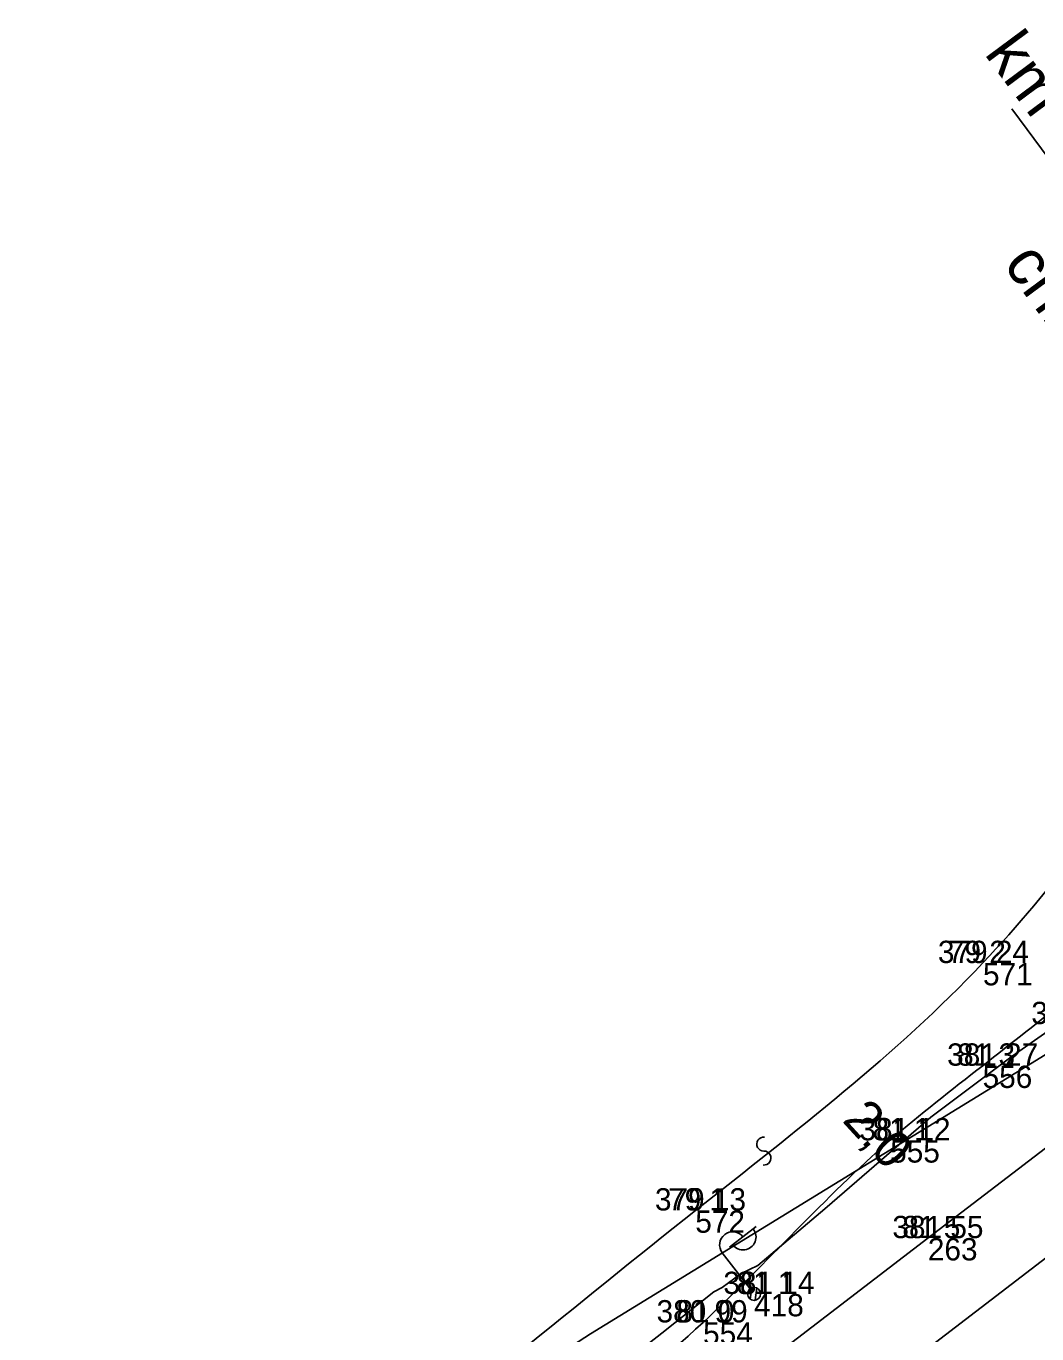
# Model space of a CAD drawing. Extents: x -514509 to -512782, y -1144610 to -1143439.
# Drawn here: x -513789.4 to -513735, y -1143931.3 to -1143860.8 of the extents above; entities that cross this region are included whole.
import ezdxf

# ---------------------------------------------------------------- set-up
doc = ezdxf.new("R2010")
doc.units = 0
for name, color, linetype in [('Vrstva 1', 7, 'Continuous'), ('Vrstva 10', 7, 'Continuous'), ('Vrstva 11', 7, 'Continuous'), ('Vrstva 18', 7, 'Continuous'), ('Vrstva 19', 7, 'Continuous'), ('Vrstva 57', 7, 'Continuous'), ('Vrstva 58', 7, 'Continuous'), ('Vrstva 59', 7, 'Continuous'), ('Vrstva 6', 7, 'Continuous'), ('Vrstva 60', 7, 'Continuous'), ('Vrstva 62', 7, 'Continuous')]:
    doc.layers.add(name, color=color, linetype=linetype)

msp = doc.modelspace()

# ---------------------------------------------------------------- linework, layer by layer
at = {"layer": 'Vrstva 1'}
msp.add_lwpolyline([(-513762.897, -1143937.295), (-513755.156, -1143931.215), (-513752.352, -1143928.991), (-513751.904, -1143928.751), (-513750.881, -1143928.002), (-513749.99, -1143927.567), (-513746.371, -1143924.523), (-513740.66, -1143919.588), (-513736.28, -1143916.302), (-513730.038, -1143911.923)], dxfattribs=at)
at = {"layer": 'Vrstva 10'}
for points in [[(-513758.996, -1143931.25), (-513726.599, -1143911.373), (-513730.516, -1143905.166)], [(-513758.996, -1143931.25), (-513726.599, -1143911.373), (-513730.516, -1143905.166)], [(-514025.149, -1144123.322), (-513986.763, -1144090.342), (-513957.919, -1144069.739), (-513914.955, -1144044.203), (-513897.091, -1144037.29), (-513901.487, -1144029.673), (-513902.648, -1144013.079), (-513904.872, -1144006.744), (-513902.386, -1144000.442), (-513898.213, -1143983.882), (-513883.45, -1143978.334), (-513880.104, -1143957.938), (-513880.595, -1143949.403), (-513873.972, -1143977.51), (-513847.31, -1143967.987), (-513854.293, -1143956.979), (-513854.953, -1143942.972), (-513846.666, -1143942.117), (-513841, -1143972.71), (-513831.435, -1143973.145), (-513796.384, -1143955.482), (-513758.996, -1143931.25)], [(-514025.149, -1144123.322), (-513986.763, -1144090.342), (-513957.919, -1144069.739), (-513914.955, -1144044.203), (-513897.091, -1144037.29), (-513901.487, -1144029.673), (-513902.648, -1144013.079), (-513904.872, -1144006.744), (-513902.386, -1144000.442), (-513898.213, -1143983.882), (-513883.45, -1143978.334), (-513880.104, -1143957.938), (-513880.595, -1143949.403), (-513873.972, -1143977.51), (-513847.31, -1143967.987), (-513854.293, -1143956.979), (-513854.953, -1143942.972), (-513846.666, -1143942.117), (-513841, -1143972.71), (-513831.435, -1143973.145), (-513796.384, -1143955.482), (-513758.996, -1143931.25)]]:
    msp.add_lwpolyline(points, dxfattribs=at)
for points in [[(-513674.274, -1143843.477), (-513674.46, -1143843.597), (-513687.396, -1143852.464), (-513702.821, -1143867.073), (-513717.154, -1143882.054), (-513727.841, -1143898.171), (-513737.859, -1143911.275), (-513753.355, -1143924.614), (-513772.465, -1143940.017), (-513793.162, -1143954.594), (-513811.59, -1143964.008), (-513831.445, -1143975.36)], [(-513808.418, -1143998.941), (-513792.063, -1143986.974), (-513776.16, -1143976.17), (-513764.915, -1143968.271), (-513753.689, -1143959.442), (-513740.521, -1143947.369), (-513724.263, -1143934.903), (-513707.902, -1143922.425), (-513689.125, -1143907.833), (-513675.979, -1143896.958), (-513671.6, -1143893.116), (-513670.058, -1143892.633), (-513668.651, -1143892.952)], [(-513754.963, -1143964.828), (-513734.448, -1143946.693), (-513721.252, -1143935.706), (-513704.018, -1143924.219), (-513687.594, -1143911.382), (-513671.785, -1143899.771)], [(-513766.691, -1143941.396), (-513752.939, -1143930.638), (-513742.864, -1143920.831), (-513737.875, -1143916.811), (-513728.639, -1143909.49)]]:
    msp.add_spline(points, degree=3, dxfattribs=at)
at = {"layer": 'Vrstva 18'}
for centre, radius, start, end in [((-513749.674, -1143921.034), 0.376, 84.36247, 270.6736), ((-513749.661, -1143921.787), 0.377, 263.68642, 91.34964)]:
    msp.add_arc(centre, radius, start, end, dxfattribs=at)
at = {"layer": 'Vrstva 19'}
msp.add_lwpolyline([(-513711.337, -1143898.914), (-513736.312, -1143865.258)], dxfattribs=at)
at = {"layer": 'Vrstva 6'}
for p, q in [((-513751.514, -1143926.588), (-513750.073, -1143925.477)), ((-513750.405, -1143928.827), (-513751.902, -1143926.888)), ((-513750.394, -1143929.39), (-513750.315, -1143928.779)), ((-513750.137, -1143929.449), (-513750.051, -1143928.784))]:
    msp.add_line(p, q, dxfattribs=at)
for points in [[(-513827.123, -1143992.273), (-513814.52, -1143984.92), (-513803.868, -1143978.359), (-513784.062, -1143964.604), (-513774.734, -1143957.987), (-513763.96, -1143949.74), (-513753.71, -1143941.89), (-513743.11, -1143933.78), (-513733.1, -1143926.12), (-513722.71, -1143918.17), (-513711.92, -1143909.9), (-513701.89, -1143902.23), (-513691.32, -1143894.14), (-513681.01, -1143886.25), (-513670.75, -1143878.4), (-513660.29, -1143870.39), (-513649.91, -1143862.61), (-513639.176, -1143854.227), (-513628.844, -1143846.318), (-513618.412, -1143838.333), (-513608.54, -1143830.777), (-513601.542, -1143825.421)], [(-513837.119, -1143999.949), (-513820.645, -1143987.315), (-513815.582, -1143983.432), (-513803.497, -1143974.164), (-513802.439, -1143973.353), (-513792.554, -1143965.771), (-513782.63, -1143958.161), (-513771.743, -1143949.811), (-513761.681, -1143942.094), (-513751.239, -1143934.086), (-513740.83, -1143926.1), (-513730.52, -1143918.22), (-513722.302, -1143911.894), (-513710.63, -1143902.943), (-513703.927, -1143897.802), (-513702.403, -1143896.634), (-513690.746, -1143887.7), (-513684.422, -1143881.665), (-513677.637, -1143875.364), (-513669.934, -1143867.896), (-513657.965, -1143856.444)]]:
    msp.add_lwpolyline(points, dxfattribs=at)
msp.add_circle((-513750.192, -1143929.105), 0.35, dxfattribs=at)
msp.add_circle((-513750.192, -1143929.105), 0.35, dxfattribs=at)
for centre, start, end in [((-513750.788, -1143926.039), 216.94625, 38.3514), ((-513751.348, -1143926.46), 37.64883, 217.64883)]:
    msp.add_arc(centre, 0.7, start, end, dxfattribs=at)
at = {"layer": 'Vrstva 60'}
for p, q in [((-513737.86, -1143911.28), (-513737.86, -1143911.28)), ((-513737.88, -1143916.81), (-513737.88, -1143916.81)), ((-513742.86, -1143920.83), (-513742.86, -1143920.83)), ((-513753.36, -1143924.61), (-513753.36, -1143924.61)), ((-513740.83, -1143926.1), (-513740.83, -1143926.1)), ((-513750.19, -1143929.11), (-513750.19, -1143929.11)), ((-513752.94, -1143930.64), (-513752.94, -1143930.64))]:
    msp.add_line(p, q, dxfattribs=at)

# ---------------------------------------------------------------- texts
at = {"layer": 'Vrstva 11'}
msp.add_text('2,0', height=2, rotation=312.54676, dxfattribs=at).set_placement((-513745.486, -1143919.782))
at = {"layer": 'Vrstva 19'}
msp.add_text('km 42,017', height=2.5, rotation=306.57765, dxfattribs=at).set_placement((-513737.826, -1143862.29))
at = {"layer": 'Vrstva 57'}
for s, p in [('79 2 ', (-513739.75, -1143911.28)), ('81 3 ', (-513739.253, -1143916.81)), ('81 1 ', (-513743.808, -1143920.83)), ('79 1 ', (-513754.824, -1143924.61)), ('81 5 ', (-513742.203, -1143926.1)), ('81 1 ', (-513751.138, -1143929.11)), ('81 0 ', (-513754.378, -1143930.64))]:
    msp.add_text(s, height=1.2, dxfattribs=at).set_placement(p)
at = {"layer": 'Vrstva 58'}
for s, p in [('379 24', (-513740.288, -1143911.28)), ('381 17', (-513735.256, -1143914.57)), ('381 27', (-513739.791, -1143916.81)), ('381 12', (-513744.516, -1143920.83)), ('379 13', (-513755.533, -1143924.61)), ('381 55', (-513742.741, -1143926.1)), ('381 14', (-513751.846, -1143929.11)), ('380 99', (-513755.446, -1143930.64))]:
    msp.add_text(s, height=1.2, dxfattribs=at).set_placement(p)
at = {"layer": 'Vrstva 59'}
for s, p in [('571', (-513737.86, -1143912.48)), ('556', (-513737.88, -1143918.01)), ('555', (-513742.86, -1143922.03)), ('572', (-513753.36, -1143925.81)), ('263', (-513740.83, -1143927.3)), ('418', (-513750.19, -1143930.31)), ('554', (-513752.94, -1143931.84))]:
    msp.add_text(s, height=1.2, dxfattribs=at).set_placement(p)
at = {"layer": 'Vrstva 62'}
msp.add_text('chrán. plast 0.15', height=2.49999, rotation=306.53681, dxfattribs=at).set_placement((-513736.818, -1143873.649))

doc.saveas('drawing.dxf')
